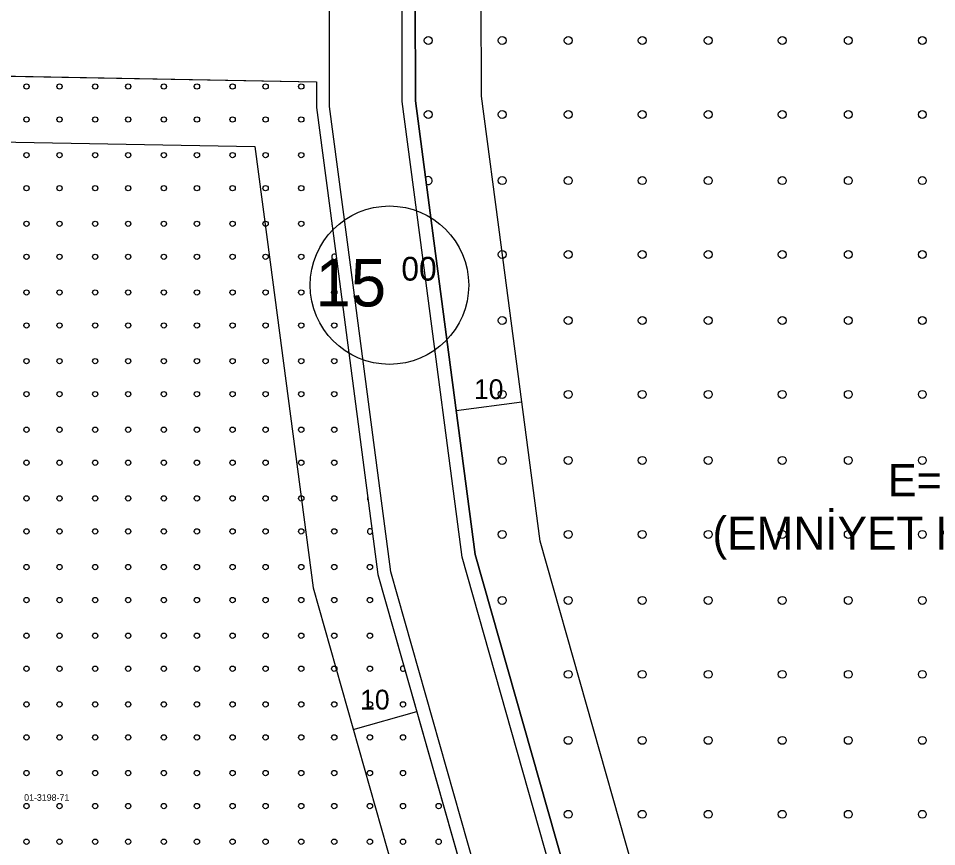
# Model space of a CAD drawing. Extents: x 419396 to 421519, y 4453567 to 4456767.
# Drawn here: x 420391.3 to 420530.3, y 4455033.3 to 4455158.8 of the extents above; entities that cross this region are included whole.
import ezdxf

# ---------------------------------------------------------------- set-up
doc = ezdxf.new("R2010")
doc.units = 0
for name, color, linetype in [('0_KADASTRO', 7, 'Continuous'), ('@PL', 7, 'Continuous'), ('ADAKENARI1000', 7, 'Continuous'), ('F_YAPI_YAKLAŞMA', 7, 'Continuous'), ('KALDIRIM', 7, 'Continuous'), ('Level 33', 7, 'Continuous'), ('Level 43', 7, 'Continuous'), ('SM_YAPILASMA', 7, 'Continuous')]:
    doc.layers.add(name, color=color, linetype=linetype)

msp = doc.modelspace()

# ---------------------------------------------------------------- linework, layer by layer
at = {"layer": '0_KADASTRO'}
for p, q in [((420451.28, 4455217.73), (420451.44, 4455146.33)), ((420451.44, 4455146.33), (420454.49, 4455123.19)), ((420454.49, 4455123.19), (420460.48, 4455077.61)), ((420460.48, 4455077.61), (420483.05, 4454997.99))]:
    msp.add_line(p, q, dxfattribs=at)
msp.add_lwpolyline([(420282.64, 4455090.54), (420297, 4455111.92), (420302.55, 4455120.28), (420304.63, 4455123.36), (420323.5, 4455151.27), (420436.44, 4455149.21), (420436.45, 4455145.33), (420439.36, 4455123.19), (420445.76, 4455074.56), (420468.34, 4454994.88), (420469.12, 4454986.67), (420468.62, 4454979.78), (420466.97, 4454973.08), (420464.21, 4454966.74), (420458.28, 4454957.65), (420451.94, 4454952.12), (420444.92, 4454948.04), (420432.46, 4454945.39), (420391.72, 4454939.02), (420368.62, 4454935.68), (420345.72, 4454934.33), (420344.76, 4455089.79)], close=True, dxfattribs=at)
at = {"layer": '@PL'}
msp.add_circle((420447.5, 4455118.39), 12, dxfattribs=at)
at = {"layer": 'ADAKENARI1000'}
for p, q in [((420451.44, 4455146.33), (420451.28, 4455217.73)), ((420323.5, 4455151.27), (420436.44, 4455149.21)), ((420436.44, 4455149.21), (420436.45, 4455145.33)), ((420454.49, 4455123.19), (420451.44, 4455146.33)), ((420436.45, 4455145.33), (420439.36, 4455123.19)), ((420439.36, 4455123.19), (420445.76, 4455074.56)), ((420460.48, 4455077.61), (420454.49, 4455123.19)), ((420485.12, 4454990.66), (420460.48, 4455077.61)), ((420445.76, 4455074.56), (420468.34, 4454994.88))]:
    msp.add_line(p, q, dxfattribs=at)
at = {"layer": 'F_YAPI_YAKLAŞMA'}
for p, q in [((420461.44, 4455147), (420461.28, 4455217.28)), ((420464.4, 4455124.49), (420461.44, 4455147)), ((420328.74, 4455141.17), (420427.14, 4455139.38)), ((420427.14, 4455139.38), (420429.44, 4455121.88)), ((420470.3, 4455079.63), (420464.4, 4455124.49)), ((420429.44, 4455121.88), (420435.94, 4455072.53)), ((420467.54, 4455100.68), (420457.62, 4455099.37)), ((420494.75, 4454993.39), (420470.3, 4455079.63)), ((420435.94, 4455072.53), (420458.47, 4454993.03)), ((420442.01, 4455051.1), (420451.63, 4455053.83))]:
    msp.add_line(p, q, dxfattribs=at)
at = {"layer": 'KALDIRIM'}
for p, q in [((420438.44, 4455145.46), (420438.28, 4455218.31)), ((420449.44, 4455146.2), (420449.28, 4455217.82)), ((420452.51, 4455122.93), (420449.44, 4455146.2)), ((420441.6, 4455121.49), (420438.44, 4455145.46)), ((420458.52, 4455077.2), (420452.51, 4455122.93)), ((420447.72, 4455074.97), (420441.6, 4455121.49)), ((420484.08, 4454987.01), (420458.52, 4455077.2)), ((420470.66, 4454994.01), (420447.72, 4455074.97))]:
    msp.add_line(p, q, dxfattribs=at)
at = {"layer": 'Level 33'}
for centre in [(420453.37, 4455155.45), (420464.57, 4455155.45), (420474.57, 4455155.45), (420485.77, 4455155.45), (420495.77, 4455155.45), (420506.97, 4455155.45), (420516.97, 4455155.45), (420528.18, 4455155.45), (420453.37, 4455144.24), (420464.57, 4455144.24), (420474.57, 4455144.24), (420485.77, 4455144.24), (420495.77, 4455144.24), (420506.97, 4455144.24), (420516.97, 4455144.24), (420528.18, 4455144.24), (420464.57, 4455134.24), (420474.57, 4455134.24), (420485.77, 4455134.24), (420495.77, 4455134.24), (420506.97, 4455134.24), (420516.97, 4455134.24), (420528.18, 4455134.24), (420464.57, 4455123.04), (420474.57, 4455123.04), (420485.77, 4455123.04), (420495.77, 4455123.04), (420506.97, 4455123.04), (420516.97, 4455123.04), (420528.18, 4455123.04), (420464.57, 4455113.04), (420474.57, 4455113.04), (420485.77, 4455113.04), (420495.77, 4455113.04), (420506.97, 4455113.04), (420516.97, 4455113.04), (420528.18, 4455113.04), (420464.57, 4455101.84), (420474.57, 4455101.84), (420485.77, 4455101.84), (420495.77, 4455101.84), (420506.97, 4455101.84), (420516.97, 4455101.84), (420528.18, 4455101.84), (420464.57, 4455091.84), (420474.57, 4455091.84), (420485.77, 4455091.84), (420495.77, 4455091.84), (420506.97, 4455091.84), (420516.97, 4455091.84), (420528.18, 4455091.84), (420464.57, 4455080.64), (420474.57, 4455080.64), (420485.77, 4455080.64), (420495.77, 4455080.64), (420506.97, 4455080.64), (420516.97, 4455080.64), (420528.18, 4455080.64), (420464.57, 4455070.64), (420474.57, 4455070.64), (420485.77, 4455070.64), (420495.77, 4455070.64), (420506.97, 4455070.64), (420516.97, 4455070.64), (420528.18, 4455070.64), (420474.57, 4455059.44), (420485.77, 4455059.44), (420495.77, 4455059.44), (420506.97, 4455059.44), (420516.97, 4455059.44), (420528.18, 4455059.44), (420474.57, 4455049.44), (420485.77, 4455049.44), (420495.77, 4455049.44), (420506.97, 4455049.44), (420516.97, 4455049.44), (420528.18, 4455049.44), (420474.57, 4455038.24), (420485.77, 4455038.24), (420495.77, 4455038.24), (420506.97, 4455038.24), (420516.97, 4455038.24), (420528.18, 4455038.24)]:
    msp.add_circle(centre, 0.6, dxfattribs=at)
msp.add_arc((420453.37, 4455134.24), 0.6, 243.4742, 131.5187, dxfattribs=at)
at = {"layer": 'Level 43'}
for centre in [(420392.55, 4455148.49), (420397.55, 4455148.49), (420402.95, 4455148.49), (420407.95, 4455148.49), (420413.35, 4455148.49), (420418.35, 4455148.49), (420423.75, 4455148.49), (420428.75, 4455148.49), (420434.15, 4455148.49), (420392.55, 4455143.49), (420397.55, 4455143.49), (420402.95, 4455143.49), (420407.95, 4455143.49), (420413.35, 4455143.49), (420418.35, 4455143.49), (420423.75, 4455143.49), (420428.75, 4455143.49), (420434.15, 4455143.49), (420392.55, 4455138.09), (420397.55, 4455138.09), (420402.95, 4455138.09), (420407.95, 4455138.09), (420413.35, 4455138.09), (420418.35, 4455138.09), (420423.75, 4455138.09), (420428.75, 4455138.09), (420434.15, 4455138.09), (420392.55, 4455133.09), (420397.55, 4455133.09), (420402.95, 4455133.09), (420407.95, 4455133.09), (420413.35, 4455133.09), (420418.35, 4455133.09), (420423.75, 4455133.09), (420428.75, 4455133.09), (420434.15, 4455133.09), (420392.55, 4455127.69), (420397.55, 4455127.69), (420402.95, 4455127.69), (420407.95, 4455127.69), (420413.35, 4455127.69), (420418.35, 4455127.69), (420423.75, 4455127.69), (420428.75, 4455127.69), (420434.15, 4455127.69), (420392.55, 4455122.69), (420397.55, 4455122.69), (420402.95, 4455122.69), (420407.95, 4455122.69), (420413.35, 4455122.69), (420418.35, 4455122.69), (420423.75, 4455122.69), (420428.75, 4455122.69), (420434.15, 4455122.69), (420392.55, 4455117.29), (420397.55, 4455117.29), (420402.95, 4455117.29), (420407.95, 4455117.29), (420413.35, 4455117.29), (420418.35, 4455117.29), (420423.75, 4455117.29), (420428.75, 4455117.29), (420434.15, 4455117.29), (420439.15, 4455117.29), (420392.55, 4455112.29), (420397.55, 4455112.29), (420402.95, 4455112.29), (420407.95, 4455112.29), (420413.35, 4455112.29), (420418.35, 4455112.29), (420423.75, 4455112.29), (420428.75, 4455112.29), (420434.15, 4455112.29), (420439.15, 4455112.29), (420392.55, 4455106.89), (420397.55, 4455106.89), (420402.95, 4455106.89), (420407.95, 4455106.89), (420413.35, 4455106.89), (420418.35, 4455106.89), (420423.75, 4455106.89), (420428.75, 4455106.89), (420434.15, 4455106.89), (420439.15, 4455106.89), (420392.55, 4455101.89), (420397.55, 4455101.89), (420402.95, 4455101.89), (420407.95, 4455101.89), (420413.35, 4455101.89), (420418.35, 4455101.89), (420423.75, 4455101.89), (420428.75, 4455101.89), (420434.15, 4455101.89), (420439.15, 4455101.89), (420392.55, 4455096.49), (420397.55, 4455096.49), (420402.95, 4455096.49), (420407.95, 4455096.49), (420413.35, 4455096.49), (420418.35, 4455096.49), (420423.75, 4455096.49), (420428.75, 4455096.49), (420434.15, 4455096.49), (420439.15, 4455096.49), (420392.55, 4455091.49), (420397.55, 4455091.49), (420402.95, 4455091.49), (420407.95, 4455091.49), (420413.35, 4455091.49), (420418.35, 4455091.49), (420423.75, 4455091.49), (420428.75, 4455091.49), (420434.15, 4455091.49), (420439.15, 4455091.49), (420392.55, 4455086.09), (420397.55, 4455086.09), (420402.95, 4455086.09), (420407.95, 4455086.09), (420413.35, 4455086.09), (420418.35, 4455086.09), (420423.75, 4455086.09), (420428.75, 4455086.09), (420434.15, 4455086.09), (420439.15, 4455086.09), (420392.55, 4455081.09), (420397.55, 4455081.09), (420402.95, 4455081.09), (420407.95, 4455081.09), (420413.35, 4455081.09), (420418.35, 4455081.09), (420423.75, 4455081.09), (420428.75, 4455081.09), (420434.15, 4455081.09), (420439.15, 4455081.09), (420392.55, 4455075.69), (420397.55, 4455075.69), (420402.95, 4455075.69), (420407.95, 4455075.69), (420413.35, 4455075.69), (420418.35, 4455075.69), (420423.75, 4455075.69), (420428.75, 4455075.69), (420434.15, 4455075.69), (420439.15, 4455075.69), (420444.55, 4455075.69), (420392.55, 4455070.69), (420397.55, 4455070.69), (420402.95, 4455070.69), (420407.95, 4455070.69), (420413.35, 4455070.69), (420418.35, 4455070.69), (420423.75, 4455070.69), (420428.75, 4455070.69), (420434.15, 4455070.69), (420439.15, 4455070.69), (420444.55, 4455070.69), (420392.55, 4455065.29), (420397.55, 4455065.29), (420402.95, 4455065.29), (420407.95, 4455065.29), (420413.35, 4455065.29), (420418.35, 4455065.29), (420423.75, 4455065.29), (420428.75, 4455065.29), (420434.15, 4455065.29), (420439.15, 4455065.29), (420444.55, 4455065.29), (420392.55, 4455060.29), (420397.55, 4455060.29), (420402.95, 4455060.29), (420407.95, 4455060.29), (420413.35, 4455060.29), (420418.35, 4455060.29), (420423.75, 4455060.29), (420428.75, 4455060.29), (420434.15, 4455060.29), (420439.15, 4455060.29), (420444.55, 4455060.29), (420392.55, 4455054.89), (420397.55, 4455054.89), (420402.95, 4455054.89), (420407.95, 4455054.89), (420413.35, 4455054.89), (420418.35, 4455054.89), (420423.75, 4455054.89), (420428.75, 4455054.89), (420434.15, 4455054.89), (420439.15, 4455054.89), (420444.55, 4455054.89), (420449.55, 4455054.89), (420392.55, 4455049.89), (420397.55, 4455049.89), (420402.95, 4455049.89), (420407.95, 4455049.89), (420413.35, 4455049.89), (420418.35, 4455049.89), (420423.75, 4455049.89), (420428.75, 4455049.89), (420434.15, 4455049.89), (420439.15, 4455049.89), (420444.55, 4455049.89), (420449.55, 4455049.89), (420392.55, 4455044.49), (420397.55, 4455044.49), (420402.95, 4455044.49), (420407.95, 4455044.49), (420413.35, 4455044.49), (420418.35, 4455044.49), (420423.75, 4455044.49), (420428.75, 4455044.49), (420434.15, 4455044.49), (420439.15, 4455044.49), (420444.55, 4455044.49), (420449.55, 4455044.49), (420392.55, 4455039.49), (420397.55, 4455039.49), (420402.95, 4455039.49), (420407.95, 4455039.49), (420413.35, 4455039.49), (420418.35, 4455039.49), (420423.75, 4455039.49), (420428.75, 4455039.49), (420434.15, 4455039.49), (420439.15, 4455039.49), (420444.55, 4455039.49), (420449.55, 4455039.49), (420454.95, 4455039.49), (420392.55, 4455034.09), (420397.55, 4455034.09), (420402.95, 4455034.09), (420407.95, 4455034.09), (420413.35, 4455034.09), (420418.35, 4455034.09), (420423.75, 4455034.09), (420428.75, 4455034.09), (420434.15, 4455034.09), (420439.15, 4455034.09), (420444.55, 4455034.09), (420449.55, 4455034.09), (420454.95, 4455034.09)]:
    msp.add_circle(centre, 0.4, dxfattribs=at)
for centre, start, end in [((420439.15, 4455127.69), 171.2245, 203.767), ((420439.15, 4455122.69), 55.3728, 319.6198), ((420444.55, 4455086.09), 148.4489, 226.5437), ((420444.55, 4455081.09), 38.8305, 336.1621), ((420449.55, 4455060.29), 69.1565, 322.4879)]:
    msp.add_arc(centre, 0.4, start, end, dxfattribs=at)

# ---------------------------------------------------------------- texts
at = {"layer": '0_KADASTRO'}
msp.add_text('01-3198-71', height=1, dxfattribs=at).set_placement((420392.19, 4455040.28))
at = {"layer": '@PL'}
for s, height, p in [('00', 3.6, (420449.3, 4455119.08)), ('15', 7.2, (420436.29, 4455115.17)), ('E=1.50', 4.9, (420522.95, 4455086.41))]:
    msp.add_text(s, height=height, dxfattribs=at).set_placement(p)
at = {"layer": 'F_YAPI_YAKLAŞMA'}
for p in [(420460.3, 4455101.13), (420443.06, 4455054.11)]:
    msp.add_text('10', height=3, dxfattribs=at).set_placement(p)
at = {"layer": 'SM_YAPILASMA'}
msp.add_text('(EMNİYET HİZMET ALANI)', height=5, dxfattribs=at).set_placement((420496.4, 4455078.33))

doc.saveas('drawing.dxf')
